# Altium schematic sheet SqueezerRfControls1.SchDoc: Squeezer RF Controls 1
size C; Organization: LIGO Laboratory; Address1: California Institute of Technology; Address2: Massachusetts Institute of Technology; SheetNumber: 32; SheetTotal: 37; DrawnBy: R.  Abbott; Engineer: R.  Abbott
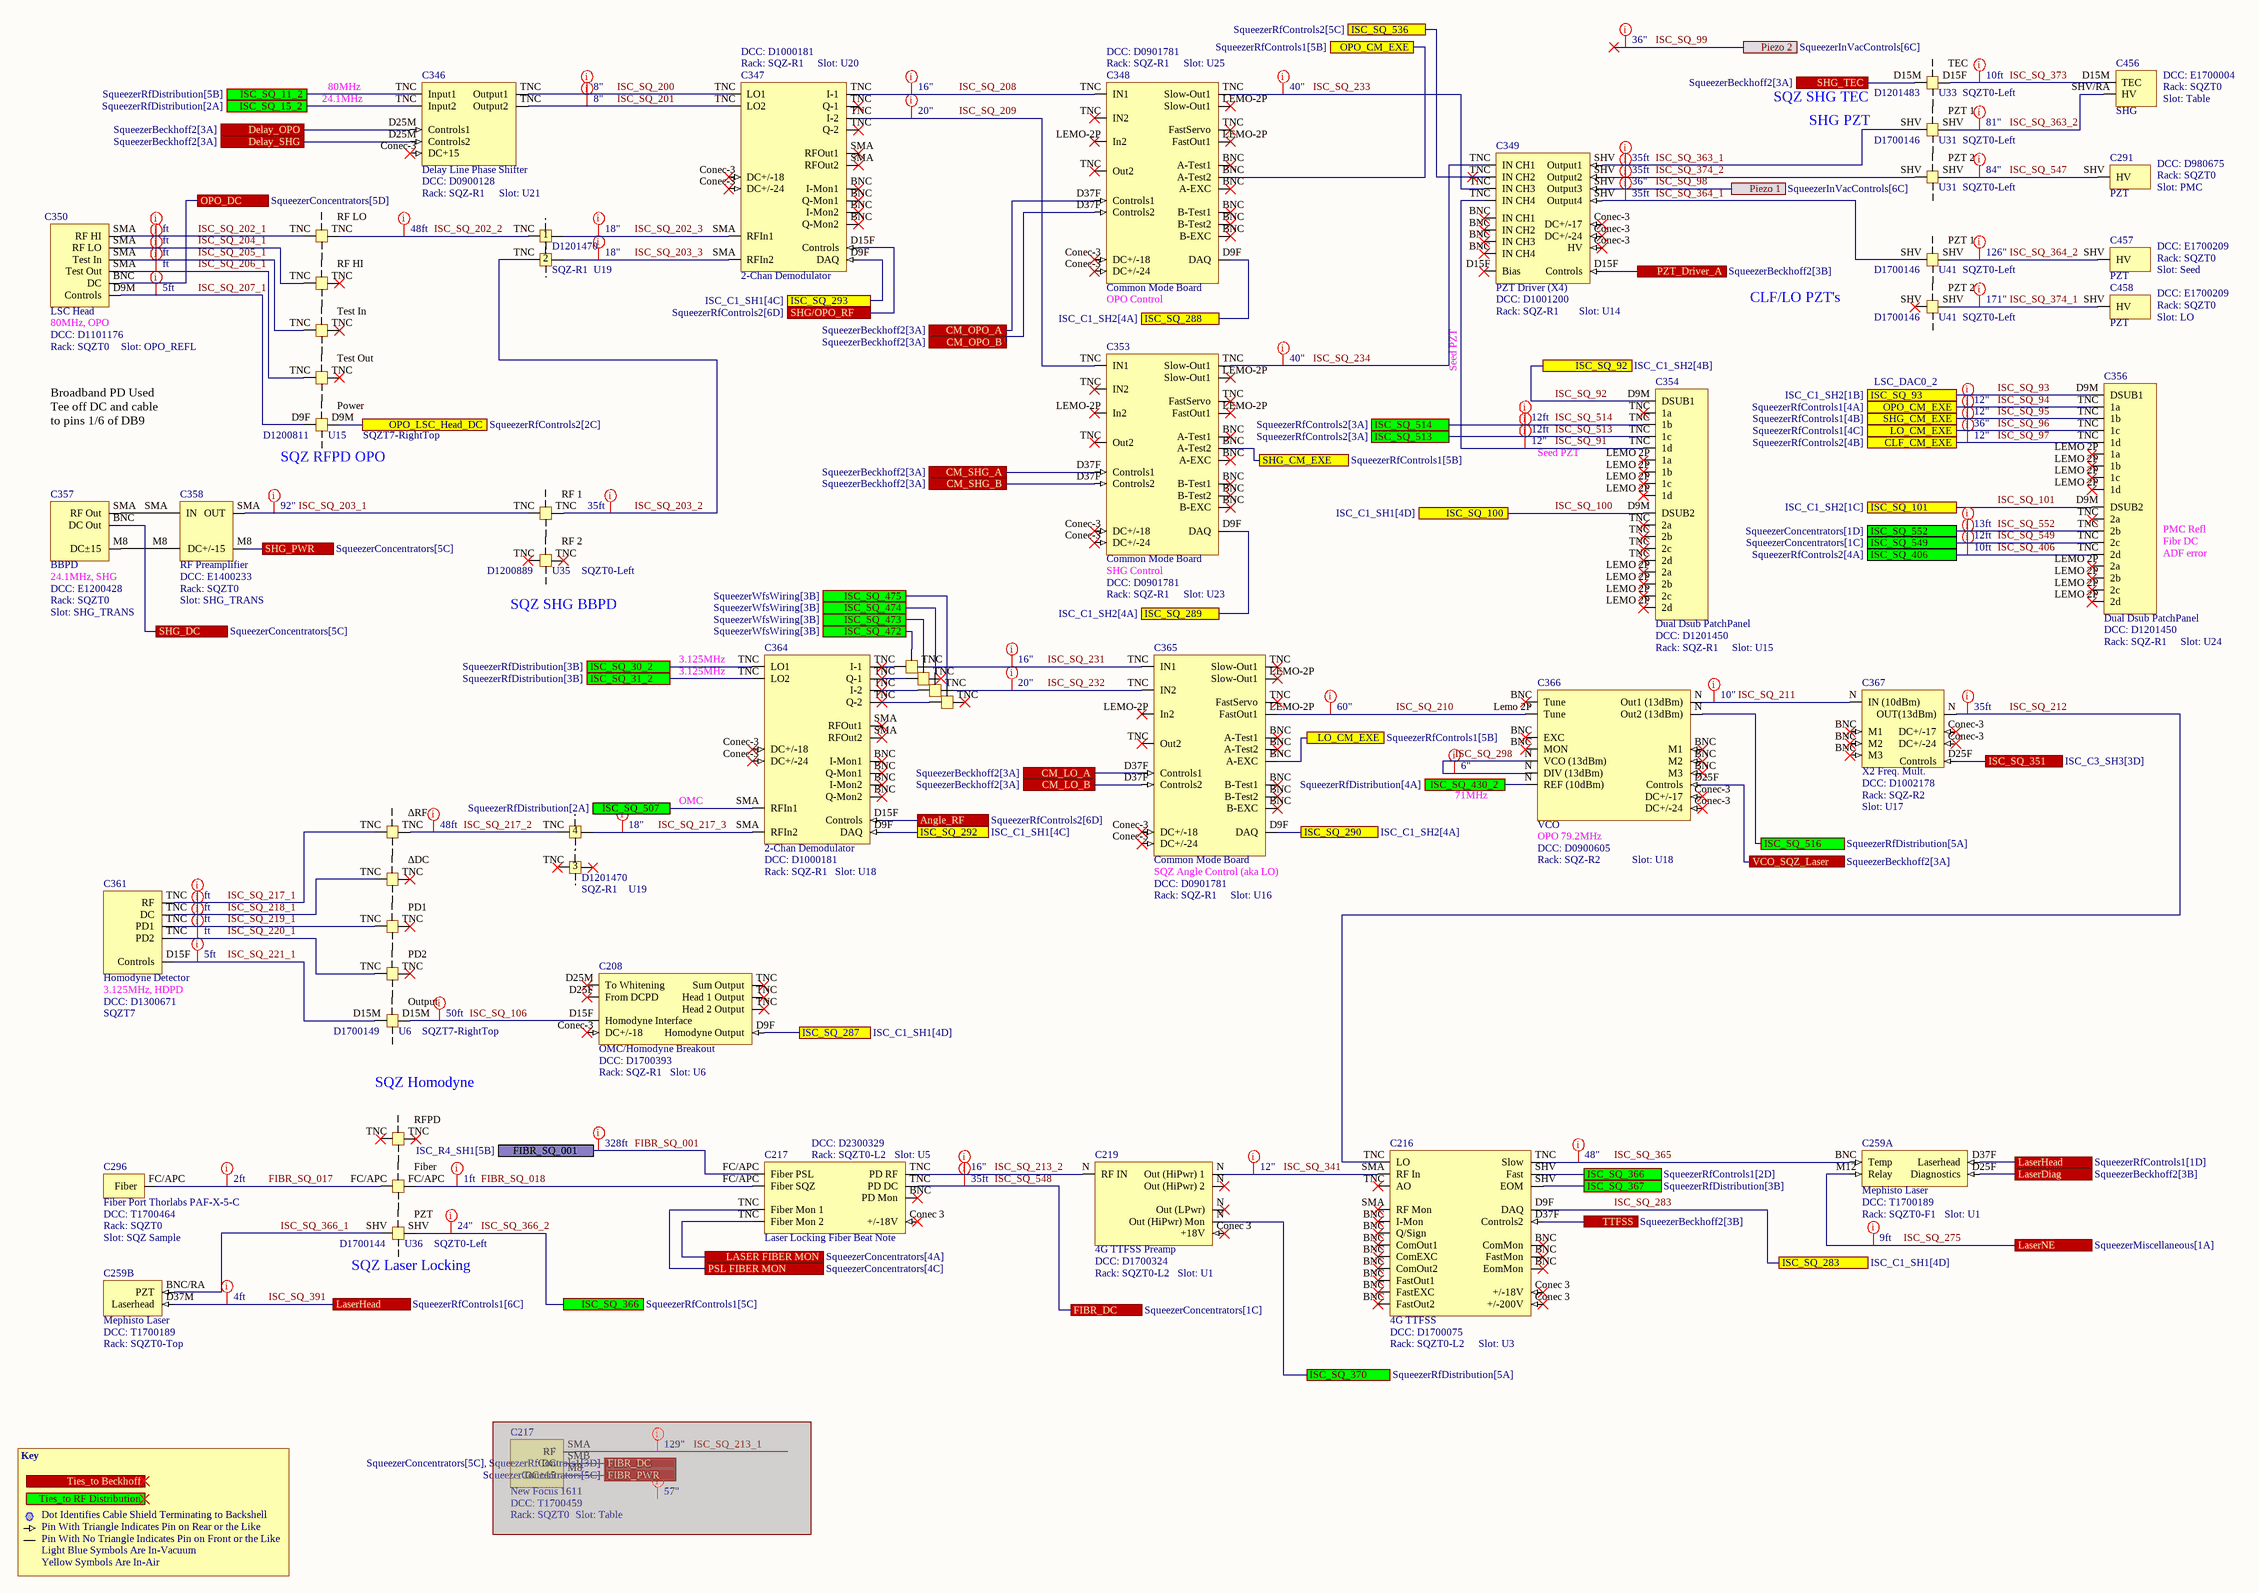
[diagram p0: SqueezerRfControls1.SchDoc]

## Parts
(Parts that share a designator on the sheet are numbered #1, #2 ... from top to bottom, then left to right.)
C208  OMC/Homodyne Breakout  DCC: D1700393  Rack: SQZ-R1  Slot: U6
C216  4G TTFSS  DCC: D1700075  Rack: SQZT0-L2  Slot: U3
C217#1  Laser Locking Fiber Beat Note  DCC: D2300329  Rack: SQZT0-L2  Slot: U5
C217#2  New Focus 1611  DCC: T1700459  Rack: SQZT0  Slot: Table  (masked out: inside a compile mask, not in the netlist)
C218  Patch Panel Laser Locking  (value not drawn)  (parts A,C,D of 4)
C219  4G TTFSS Preamp  DCC: D1700324  Rack: SQZT0-L2  Slot: U1
C259  Mephisto Laser  DCC: T1700189  Rack: SQZT0-F1  Slot: U1  (parts A,B of 2)
C263  Tee  (value not drawn)
C264  Tee  (value not drawn)
C265  Tee  (value not drawn)
C266  Tee  (value not drawn)
C291  PZT  DCC: D980675  Rack: SQZT0  Slot: PMC
C296  Fiber Port Thorlabs PAF-X-5-C  DCC: T1700464  Rack: SQZT0  Slot: SQZ Sample
C346  Delay Line Phase Shifter  DCC: D0900128  Rack: SQZ-R1  Slot: U21
C347  2-Chan Demodulator  DCC: D1000181  Rack: SQZ-R1  Slot: U20
C348  Common Mode Board  DCC: D0901781  Rack: SQZ-R1  Slot: U25
C349  PZT Driver (X4)  DCC: D1001200  Rack: SQZ-R1  Slot: U14
C350  LSC Head  DCC: D1101176  Rack: SQZT0  Slot: OPO_REFL
C351  Patch Panel Dual Frequency LSC RFPD  (value not drawn)  (parts A,B,C,D,E of 5)
C352  Patch Panel TNC 1U  (value not drawn)  (parts A,B,C,D of 4)
C353  Common Mode Board  DCC: D0901781  Rack: SQZ-R1  Slot: U23
C354  Dual Dsub PatchPanel  DCC: D1201450  Rack: SQZ-R1  Slot: U15
C356  Dual Dsub PatchPanel  DCC: D1201450  Rack: SQZ-R1  Slot: U24
C357  BBPD  DCC: E1200428  Rack: SQZT0  Slot: SHG_TRANS
C358  RF Preamplifier  DCC: E1400233  Rack: SQZT0  Slot: SHG_TRANS
C359  Patch Panel Broadband PD  (value not drawn)  (parts A,B of 2)
C361  Homodyne Detector  DCC: D1300671  Rack: SQZT7
C362  Patch Panel Homodyne  (value not drawn)  (parts A,B,C,D,E of 5)
C364  2-Chan Demodulator  DCC: D1000181  Rack: SQZ-R1  Slot: U18
C365  Common Mode Board  DCC: D0901781  Rack: SQZ-R1  Slot: U16
C366  VCO  DCC: D0900605  Rack: SQZ-R2  Slot: U18
C367  X2 Freq. Mult.  DCC: D1002178  Rack: SQZ-R2  Slot: U17
C453  DCC: D1201483  Rack: SQZT0-Left  Slot: U33  (hidden comment: Patch Panel TEC Driver)
C454  DCC: D1700146  Rack: SQZT0-Left  Slot: U31  (hidden comment: Patch Panel PZT)  (parts A,B of 2)
C455  DCC: D1700146  Rack: SQZT0-Left  Slot: U41  (hidden comment: Patch Panel PZT)  (parts A,B of 2)
C456  SHG  DCC: E1700004  Rack: SQZT0  Slot: Table
C457  PZT  DCC: E1700209  Rack: SQZT0  Slot: Seed
C458  PZT  DCC: E1700209  Rack: SQZT0  Slot: LO

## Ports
Angle_RF (see SqueezerRfControls2[6D]), CLF_CM_EXE (see SqueezerRfControls2[4B]), CM_LO_A (see SqueezerBeckhoff2[3A]), CM_LO_B (see SqueezerBeckhoff2[3A]), CM_OPO_A (see SqueezerBeckhoff2[3A]), CM_OPO_B (see SqueezerBeckhoff2[3A]), CM_SHG_A (see SqueezerBeckhoff2[3A]), CM_SHG_B (see SqueezerBeckhoff2[3A]), Delay_OPO (see SqueezerBeckhoff2[3A]), Delay_SHG (see SqueezerBeckhoff2[3A]), FIBR_DC (see SqueezerConcentrators[1C]), FIBR_DC (see SqueezerConcentrators[5C], SqueezerRfControls1[3D]), FIBR_PWR (see SqueezerConcentrators[5C]), FIBR_SQ_001 (see ISC_R4_SH1[5B]), ISC_SQ_11_2 (see SqueezerRfDistribution[5B]), ISC_SQ_15_2 (see SqueezerRfDistribution[2A]), ISC_SQ_30_2 (see SqueezerRfDistribution[3B]), ISC_SQ_31_2 (see SqueezerRfDistribution[3B]), ISC_SQ_92 (see ISC_C1_SH2[4B]), ISC_SQ_93 (see ISC_C1_SH2[1B]), ISC_SQ_100 (see ISC_C1_SH1[4D]), ISC_SQ_101 (see ISC_C1_SH2[1C]), ISC_SQ_283 (see ISC_C1_SH1[4D]), ISC_SQ_287 (see ISC_C1_SH1[4D]), ISC_SQ_288 (see ISC_C1_SH2[4A]), ISC_SQ_289 (see ISC_C1_SH2[4A]), ISC_SQ_290 (see ISC_C1_SH2[4A]), ISC_SQ_292 (see ISC_C1_SH1[4C]), ISC_SQ_293 (see ISC_C1_SH1[4C]), ISC_SQ_351 (see ISC_C3_SH3[3D]), ISC_SQ_366 (see SqueezerRfControls1[2D]), ISC_SQ_366 (see SqueezerRfControls1[5C]), ISC_SQ_367 (see SqueezerRfDistribution[3B]), ISC_SQ_370 (see SqueezerRfDistribution[5A]), ISC_SQ_406 (see SqueezerRfControls2[4A]), ISC_SQ_430_2 (see SqueezerRfDistribution[4A]), ISC_SQ_472 (see SqueezerWfsWiring[3B]), ISC_SQ_473 (see SqueezerWfsWiring[3B]), ISC_SQ_474 (see SqueezerWfsWiring[3B]), ISC_SQ_475 (see SqueezerWfsWiring[3B]), ISC_SQ_507 (see SqueezerRfDistribution[2A]), ISC_SQ_513 (see SqueezerRfControls2[3A]), ISC_SQ_514 (see SqueezerRfControls2[3A]), ISC_SQ_516 (see SqueezerRfDistribution[5A]), ISC_SQ_536 (see SqueezerRfControls2[5C]), ISC_SQ_549 (see SqueezerConcentrators[1C]), ISC_SQ_552 (see SqueezerConcentrators[1D]), LASER FIBER MON (see SqueezerConcentrators[4A]), LaserDiag (see SqueezerBeckhoff2[3B]), LaserHead (see SqueezerRfControls1[1D]), LaserHead (see SqueezerRfControls1[6C]), LaserNE (see SqueezerMiscellaneous[1A]), LO_CM_EXE (see SqueezerRfControls1[4C]), LO_CM_EXE (see SqueezerRfControls1[5B]), OPO_CM_EXE (see SqueezerRfControls1[4A]), OPO_CM_EXE (see SqueezerRfControls1[5B]), OPO_DC (see SqueezerConcentrators[5D]), OPO_LSC_Head_DC (see SqueezerRfControls2[2C]), Piezo 1 (see SqueezerInVacControls[6C]), Piezo 2 (see SqueezerInVacControls[6C]), PSL FIBER MON (see SqueezerConcentrators[4C]), PZT_Driver_A (see SqueezerBeckhoff2[3B]), SHG/OPO_RF (see SqueezerRfControls2[6D]), SHG_CM_EXE (see SqueezerRfControls1[4B]), SHG_CM_EXE (see SqueezerRfControls1[5B]), SHG_DC (see SqueezerConcentrators[5C]), SHG_PWR (see SqueezerConcentrators[5C]), SHG_TEC (see SqueezerBeckhoff2[3A]), Ties_to Beckhoff, Ties_to RF Distribution, TTFSS (see SqueezerBeckhoff2[3B]), VCO_SQZ_Laser (see SqueezerBeckhoff2[3A])

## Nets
Angle_RF: C364.D15F(Controls) ; port Angle_RF
CM_LO_A: C365.D37F(Controls1) ; port CM_LO_A
CM_LO_B: C365.D37F(Controls2) ; port CM_LO_B
CM_OPO_A: C348.D37F(Controls1) ; port CM_OPO_A
CM_OPO_B: C348.D37F(Controls2) ; port CM_OPO_B
CM_SHG_A: C353.D37F(Controls1) ; port CM_SHG_A
CM_SHG_B: C353.D37F(Controls2) ; port CM_SHG_B
Delay_OPO: C346.D25M(Controls1) ; port Delay_OPO
Delay_SHG: C346.D25M(Controls2) ; port Delay_SHG
FIBR_SQ_001: C217#1.FC/APC(Fiber_PSL) ; port FIBR_SQ_001
FIBR_SQ_017: C218.FC/APC(Fiber) C296.FC/APC(Fiber)
FIBR_SQ_018: C217#1.FC/APC(Fiber_SQZ) C218.FC/APC(Fiber)
ISC_SQ_11_2: C346.TNC(Input1) ; port ISC_SQ_11_2
ISC_SQ_15_2: C346.TNC(Input2) ; port ISC_SQ_15_2
ISC_SQ_30_2: C364.TNC(LO1) ; port ISC_SQ_30_2
ISC_SQ_31_2: C364.TNC(LO2) ; port ISC_SQ_31_2
ISC_SQ_91: C349.TNC(IN_CH4) C354.TNC(1d)
ISC_SQ_92: C354.D9M(DSUB1) ; port ISC_SQ_92
ISC_SQ_93: C356.D9M(DSUB1) ; port ISC_SQ_93
ISC_SQ_94: C348.BNC(A-Test1) C356.TNC(1a) ; port OPO_CM_EXE
ISC_SQ_95: C353.BNC(A-Test1) C356.TNC(1b) ; port SHG_CM_EXE
ISC_SQ_96: C356.TNC(1c) C365.BNC(A-Test1) ; port LO_CM_EXE
ISC_SQ_97: C356.TNC(1d) ; port CLF_CM_EXE
ISC_SQ_98: C349.SHV(Output3) ; port Piezo 1
ISC_SQ_100: C354.D9M(DSUB2) ; port ISC_SQ_100
ISC_SQ_101: C356.D9M(DSUB2) ; port ISC_SQ_101
ISC_SQ_106: C208.D15F(Homodyne_Interface) C362.D15M(Output)
ISC_SQ_200: C346.TNC(Output1) C347.TNC(LO1)
ISC_SQ_201: C346.TNC(Output2) C347.TNC(LO2)
ISC_SQ_202_1: C350.SMA(RF_HI) C351.TNC(RFLO)
ISC_SQ_202_2: C351.TNC(RFLO) C352.TNC
ISC_SQ_202_3: C347.SMA(RFOut1) C352.TNC
ISC_SQ_203_1: C358.SMA(OUT) C359.TNC(RF1)
ISC_SQ_203_2: C352.TNC C359.TNC(RF1)
ISC_SQ_203_3: C347.SMA(RFIn2) C352.TNC
ISC_SQ_204_1: C350.SMA(RF_LO) C351.TNC(RFHI)
ISC_SQ_205_1: C350.SMA(Test_In) C351.TNC(TestIn)
ISC_SQ_206_1: C350.SMA(Test_Out) C351.TNC(TestOut)
ISC_SQ_207_1: C350.D9M(Controls) C351.D9F(Power)
ISC_SQ_208: C347.TNC(I-1) C348.TNC(IN1)
ISC_SQ_209: C347.TNC(I-2) C353.TNC(IN1)
ISC_SQ_210: C365.LEMO-2P(In2) C366.Lemo_2P(Tune)
ISC_SQ_211: C366.N(Out1_(13dBm)) C367.N(IN_(10dBm))
ISC_SQ_212: C216.TNC(LO) C367.N(OUT(13dBm))
ISC_SQ_213_2: C217#1.TNC(PD_RF) C219.N(RF_IN)
ISC_SQ_217_1: C361.TNC(RF) C362.TNC(?RF)
ISC_SQ_217_2: C352.TNC C362.TNC(?RF)
ISC_SQ_217_3: C352.TNC C364.SMA(RFIn2)
ISC_SQ_218_1: C361.TNC(DC) C362.TNC(?DC)
ISC_SQ_219_1: C361.TNC(PD1) C362.TNC(PD1)
ISC_SQ_220_1: C361.TNC(PD2) C362.TNC(PD2)
ISC_SQ_221_1: C361.D15F(Controls) C362.D15M(Output)
ISC_SQ_231: C263.TNC C365.TNC(IN1)
ISC_SQ_232: C265.TNC C365.TNC(IN2)
ISC_SQ_233: C348.TNC(Slow-Out1) C349.TNC(IN_CH3)
ISC_SQ_234: C349.TNC(IN_CH1) C353.TNC(Slow-Out1)
ISC_SQ_275: C259.M12(Relay) ; port LaserNE
ISC_SQ_283: C216.D9F(DAQ) ; port ISC_SQ_283
ISC_SQ_287: C208.D9F(Homodyne_Output) ; port ISC_SQ_287
ISC_SQ_288: C348.D9F(DAQ) ; port ISC_SQ_288
ISC_SQ_289: C353.D9F(DAQ) ; port ISC_SQ_289
ISC_SQ_290: C365.D9F(DAQ) ; port ISC_SQ_290
ISC_SQ_292: C364.D9F(DAQ) ; port ISC_SQ_292
ISC_SQ_293: C347.D9F(DAQ) ; port ISC_SQ_293
ISC_SQ_298: C366.N(VCO_(13dBm))
ISC_SQ_341: C216.SMA(RF_In) C219.N(Out_(HiPwr)_1)
ISC_SQ_351: C367.D25F(Controls) ; port ISC_SQ_351
ISC_SQ_363_1: C349.SHV(Output1) C454.SHV(PZT1)
ISC_SQ_363_2: C454.SHV(PZT1) C456.SHV/RA(HV)
ISC_SQ_364_1: C349.SHV(Output4) C455.SHV(PZT1)
ISC_SQ_364_2: C455.SHV(PZT1) C457.SHV(HV)
ISC_SQ_365: C216.TNC(Slow) C259.BNC(Temp)
ISC_SQ_366_1: C218.SHV(PZT) C259.BNC/RA(PZT)
ISC_SQ_366_2: C216.SHV(Fast) C218.SHV(PZT) ; port ISC_SQ_366
ISC_SQ_367: C216.SHV(EOM) ; port ISC_SQ_367
ISC_SQ_370: C219.N(Out_(HiPwr)_Mon) ; port ISC_SQ_370
ISC_SQ_373: C453.D15F(TEC) C456.D15M(TEC)
ISC_SQ_374_1: C455.SHV(PZT2) C458.SHV(HV)
ISC_SQ_374_2: C349.SHV(Output2) C454.SHV(PZT2)
ISC_SQ_391: C259.D37F(Laserhead) C259.D37M(Laserhead) ; port LaserHead
ISC_SQ_406: C356.TNC(2d) ; port ISC_SQ_406
ISC_SQ_430_2: C366.N(REF_(10dBm)) ; port ISC_SQ_430_2
ISC_SQ_472: C263.TNC ; port ISC_SQ_472
ISC_SQ_473: C264.TNC ; port ISC_SQ_473
ISC_SQ_474: C265.TNC ; port ISC_SQ_474
ISC_SQ_475: C266.TNC ; port ISC_SQ_475
ISC_SQ_507: C364.SMA(RFOut1) ; port ISC_SQ_507
ISC_SQ_513: C354.TNC(1c) ; port ISC_SQ_513
ISC_SQ_514: C354.TNC(1a) ; port ISC_SQ_514
ISC_SQ_516: C366.N(Out2_(13dBm)) ; port ISC_SQ_516
ISC_SQ_536: C349.TNC(IN_CH2) ; port ISC_SQ_536
ISC_SQ_547: C291.SHV(HV) C454.SHV(PZT2)
ISC_SQ_548: C217#1.TNC(PD_DC) ; port FIBR_DC
ISC_SQ_549: C356.TNC(2c) ; port ISC_SQ_549
ISC_SQ_552: C356.TNC(2b) ; port ISC_SQ_552
LASER FIBER MON: C217#1.TNC(Fiber_Mon_2) ; port LASER FIBER MON
LaserDiag: C259.D25F(Diagnostics) ; port LaserDiag
OPO_DC: C350.BNC(DC) ; port OPO_DC
OPO_LSC_Head_DC: C351.D9M(Power) ; port OPO_LSC_Head_DC
PSL FIBER MON: C217#1.TNC(Fiber_Mon_1) ; port PSL FIBER MON
PZT_Driver_A: C349.D15F(Controls) ; port PZT_Driver_A
SHG/OPO_RF: C347.D15F(Controls) ; port SHG/OPO_RF
SHG_DC: C357.BNC(DC_Out) ; port SHG_DC
SHG_PWR: C358.M8(DC+/-15) ; port SHG_PWR
SHG_TEC: C453.D15M(TEC) ; port SHG_TEC
TTFSS: C216.D37F(Controls2) ; port TTFSS
VCO_SQZ_Laser: C366.D25F(Controls) ; port VCO_SQZ_Laser
NetC263_TNC: C263.TNC C364.TNC(I-1)
NetC264_TNC: C264.TNC C364.TNC(Q-1)
NetC265_TNC: C265.TNC C364.TNC(I-2)
NetC266_TNC: C266.TNC C364.TNC(Q-2)
NetC357_M8: C357.M8(DC±15) C358.M8(DC+/-15)
NetC357_SMA: C357.SMA(RF_Out) C358.SMA(IN)

Not connected (* = marked no-connect by the designer): C208 Conec-3(DC+/-18)* D25F(From_DCPD)* D25M(To_Whitening)* TNC(Head_1_Output)*; C216 BNC(FastEXC)* Conec 3(+/-200V)*; C217#1 BNC(PD_Mon)* Conec 3(+/-18V)*; C218 TNC(RFPD)*; C219 Conec 3(+18V)*; C346 Conec-3(DC+15)*; C347 BNC(I-Mon1)* Conec-3(DC+/-18)*; C348 Conec-3(DC+/-18)* LEMO-2P(In2)*; C349 BNC(IN_CH1)* Conec-3(DC+/-17)*; C353 Conec-3(DC+/-18)* LEMO-2P(In2)*; C354 LEMO 2P(1a)*; C356 LEMO 2P(1a)*; C364 BNC(I-Mon1)* Conec-3(DC+/-18)*; C365 Conec-3(DC+/-18)*; C366 BNC(Tune)* Conec-3(DC+/-17)*; C367 BNC(M1)* Conec-3(DC+/-17)*

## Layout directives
Length: 8": ISC_SQ_200, ISC_SQ_201
Length: ft: ISC_SQ_202_1, ISC_SQ_204_1, ISC_SQ_205_1, ISC_SQ_206_1, ISC_SQ_217_1, ISC_SQ_218_1, ISC_SQ_219_1, ISC_SQ_220_1
Length: 92": ISC_SQ_203_1
Length: 35ft: ISC_SQ_203_2, ISC_SQ_212, ISC_SQ_363_1, ISC_SQ_364_1, ISC_SQ_374_2, ISC_SQ_548
Length: 48ft: ISC_SQ_202_2, ISC_SQ_217_2
Length: 5ft: ISC_SQ_207_1, ISC_SQ_221_1
Length: 16": ISC_SQ_208, ISC_SQ_213_2, ISC_SQ_231
Length: 20": ISC_SQ_209, ISC_SQ_232
Length: 40": ISC_SQ_233, ISC_SQ_234
Length: 10": ISC_SQ_211
Length: 60": ISC_SQ_210
Length: 18": ISC_SQ_202_3, ISC_SQ_203_3, ISC_SQ_217_3
Length: 12": ISC_SQ_91, ISC_SQ_94, ISC_SQ_95, ISC_SQ_97, ISC_SQ_341
Length: 36": ISC_SQ_96, ISC_SQ_98, ISC_SQ_99
Length: 6": ISC_SQ_298
Length: 126": ISC_SQ_364_2
Length: 171": ISC_SQ_374_1
Length: 10ft: ISC_SQ_373, ISC_SQ_406
Length: 81": ISC_SQ_363_2
Length: 129": (no net found under the mark)
Length: 48": ISC_SQ_365
Length: 24": ISC_SQ_366_2
Length: 57": (no net found under the mark)
Length: 4ft: ISC_SQ_391
Length: 9ft: ISC_SQ_275
Length: 50ft: ISC_SQ_106
Length: 12ft: ISC_SQ_513, ISC_SQ_514, ISC_SQ_549
Length: 84": ISC_SQ_547
Length: 328ft: FIBR_SQ_001
Length: 1ft: FIBR_SQ_018
Length: 2ft: FIBR_SQ_017
Length: 13ft: ISC_SQ_552

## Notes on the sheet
- 24.1MHz
- 80MHz
- SQZ SHG TEC
- SHG PZT
- (near C350) 80MHz, OPO
- (near C348) OPO Control
- CLF/LO PZT's
- Seed PZT
- LSC_DAC0_2
- Broadband PD Used
  Tee off DC and cable
  to pins 1/6 of DB9
- (near C351) SQZ RFPD OPO
- (near C357) 24.1MHz, SHG
- (near C353) SHG Control
- ADF error
- Fibr DC
- PMC Refl
- (near C359) SQZ SHG BBPD
- (near C364) 3.125MHz
- OMC
- 71MHz
- (near C365) SQZ Angle Control (aka LO)
- (near C366) OPO 79.2MHz
- (near C361) 3.125MHz, HDPD
- SQZ Homodyne
- (near C218) SQZ Laser Locking
- Key
- Dot Identifies Cable Shield Terminating to Backshell
- Pin With Triangle Indicates Pin on Rear or the Like
- Pin With No Triangle Indicates Pin on Front or the Like
- Light Blue Symbols Are In-Vacuum
- Yellow Symbols Are In-Air

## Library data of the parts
C208 = 3.125MHz OMC/Homodyne Breakout: Serial: Sxxxxxxx; System: ISC
C216 = 4G TTFSS: Serial: Sxxxxxxx; System: ISC
C217#1 = Laser Locking Fiber Beat Note: Serial: Sxxxxxxx; System: ISC
C217#2 = New Focus 1611: Serial: Sxxxxxxx; System: ISC
C218 = Patch Panel Laser Locking: Patch Panel (D1700144); Serial: Sxxxxxxx; System: ISC; Rack: SQZT0-Left; Slot: U36
C219 = 4G TTFSS Preamp: Serial: Sxxxxxxx; System: ISC
C259 = Mephisto 1000NE: Serial: Sxxxxxxx; System: ISC
C263-C266 = TNC Tee: Tee (TNC); Serial: Sxxxxxxx; System: ISC; Rack: SQZ-R1; Slot: U18
C291 C457 C458 = PZT: Serial: Sxxxxxxx; System: ISC
C296 = Fiber Port Thorlabs PAF Series: Serial: Sxxxxxxx; System: ISC
C346 = DelayLinePhaseShifter: Serial: Sxxxxxxx; System: ISC
C347 C364 = 2-Chan Demod: Serial: Sxxxxxxx; System: ISC
C348 C353 C365 = CommonModeBoard: Serial: Sxxxxxxx; System: ISC
C349 = PZT Driver (X4): Serial: Sxxxxxxx; System: ISC
C350 = LSC Head: Serial: Sxxxxxxx; System: ISC
C351 = Patch Panel Dual Frequency LSC RFPD: Patch Panel (D1200811); Serial: Sxxxxxxx; System: ISC; Rack: SQZT7-RightTop; Slot: U15
C352 = Patch Panel TNC 1U: Patch Panel (D1201470); Serial: Sxxxxxxx; System: ISC; Rack: SQZ-R1; Slot: U19
C354 C356 = Dual Dsub PatchPanel: Serial: Sxxxxxxx; System: ISC
C357 = BBPD: Serial: Sxxxxxxx; System: ISC
C358 = RF Preamplifier: Low Noise RF Preamplifier; Serial: Sxxxxxxx; System: ISC
C359 = Patch Panel Broadband PD: Patch Panel (D1200889); Serial: Sxxxxxxx; System: ISC; Rack: SQZT0-Left; Slot: U35
C361 = Homodyne Detector: Serial: Sxxxxxxx; System: ISC; Slot: On Table
C362 = Patch Panel Homodyne: Patch Panel (D1700149); Serial: Sxxxxxxx; System: ISC; Rack: SQZT7-RightTop; Slot: U6
C366 = VCO: Serial: Sxxxxxxx; System: ISC
C367 = X2 Freq. Mult.: Serial: Sxxxxxxx; System: ISC
C453 = Patch Panel TEC Driver: Patch Panel (D1201483); Serial: Sxxxxxxx; System: ISC
C454 C455 = Patch Panel PZT: Patch Panel (D1700146); Serial: Sxxxxxxx; System: ISC
C456 = SHG: Serial: Sxxxxxxx; System: ISC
